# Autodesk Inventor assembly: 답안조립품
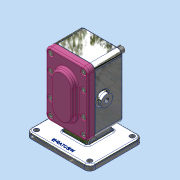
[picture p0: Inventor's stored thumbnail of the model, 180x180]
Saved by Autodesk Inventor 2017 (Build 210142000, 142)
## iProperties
Part Number: 답안조립품
Material: 일반
Document SubType Name: Assembly
Designer: MRC
Author: MRC
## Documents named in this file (11)
- C:\Users\MRC\Desktop\700407V1039\답안조립품.iam
- C:\Users\MRC\Desktop\700407V1039\본체.ipt
- C:\Users\MRC\Desktop\700407V1039\개스킷.ipt
- C:\Users\MRC\Desktop\700407V1039\메인축.ipt
- C:\Users\MRC\Desktop\700407V1039\베어링부시.ipt
- C:\Users\MRC\Desktop\700407V1039\볼트 M5.ipt
- C:\Users\MRC\Desktop\700407V1039\서브축.ipt
- C:\Users\MRC\Desktop\700407V1039\스퍼기어.ipt
- C:\Users\MRC\Desktop\700407V1039\오일 실 16 28 7.ipt
- C:\Users\MRC\Desktop\700407V1039\커버.ipt
- C:\Users\MRC\Desktop\700407V1039\키 6 x 6 x 18.ipt
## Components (1 placed, 1 different names)
1. 개스킷:1
